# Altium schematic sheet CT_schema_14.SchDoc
size 632 x 434 mm
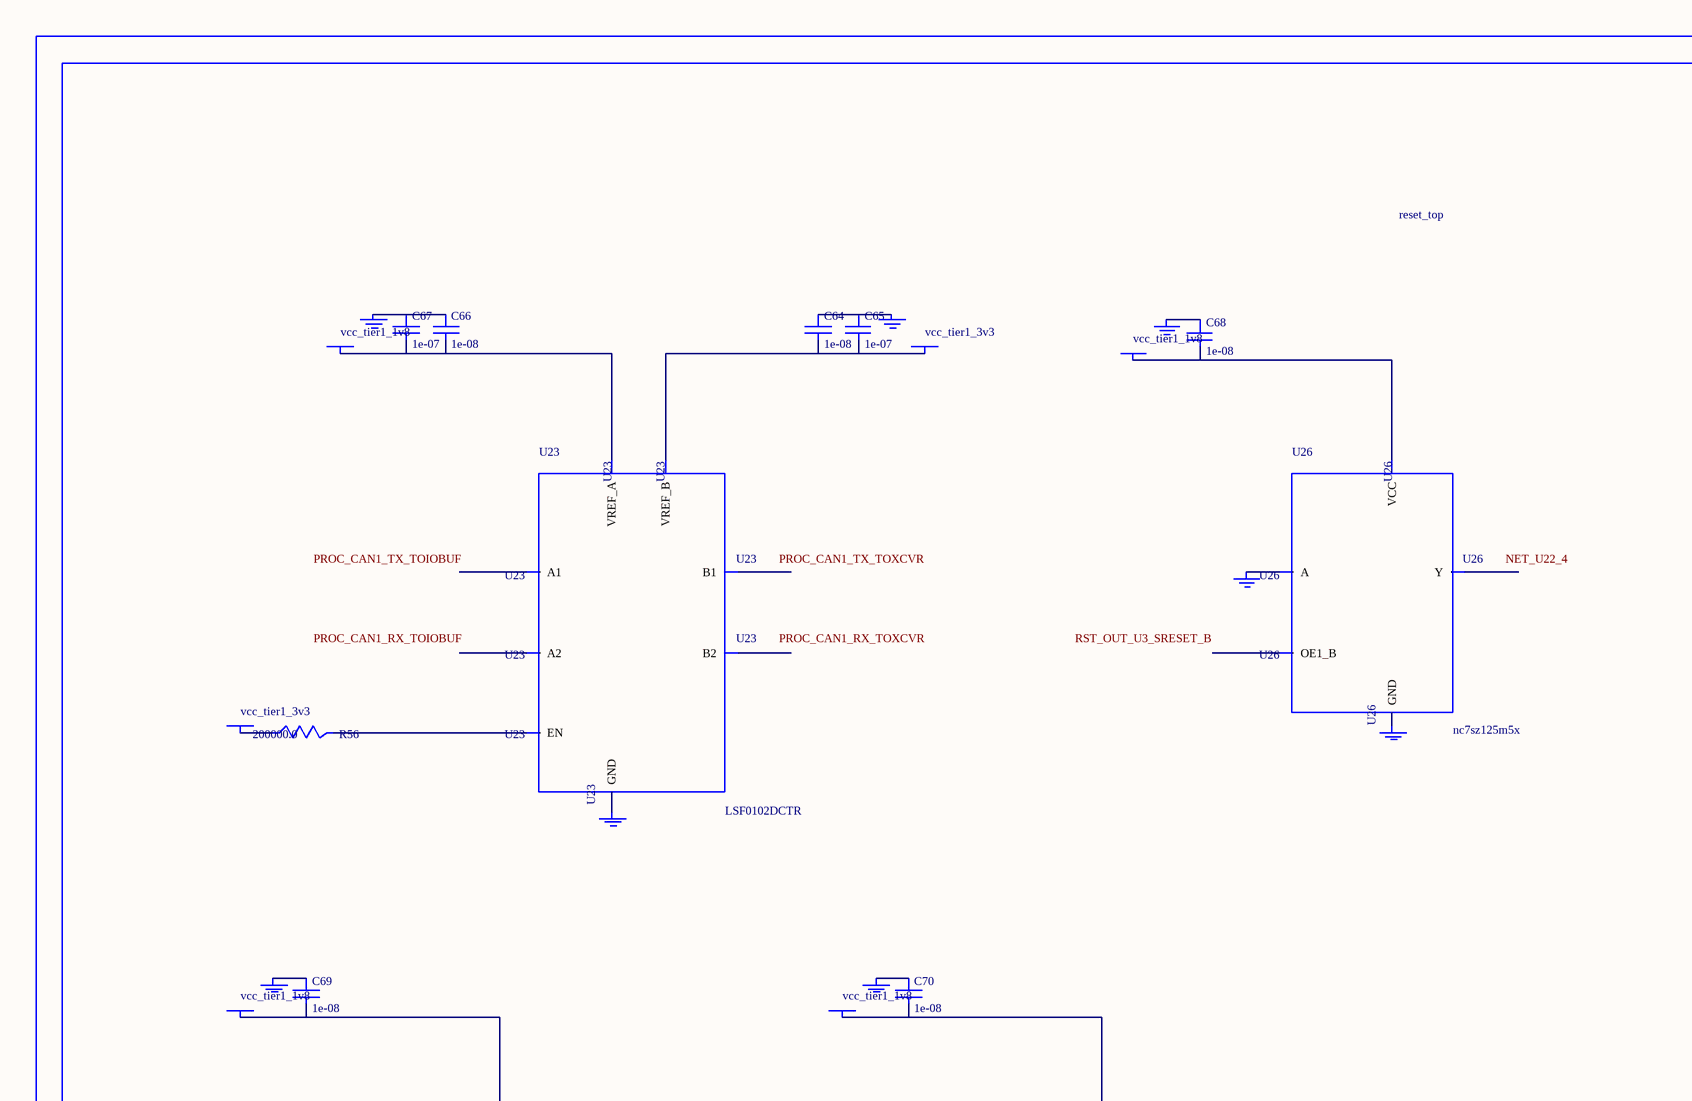
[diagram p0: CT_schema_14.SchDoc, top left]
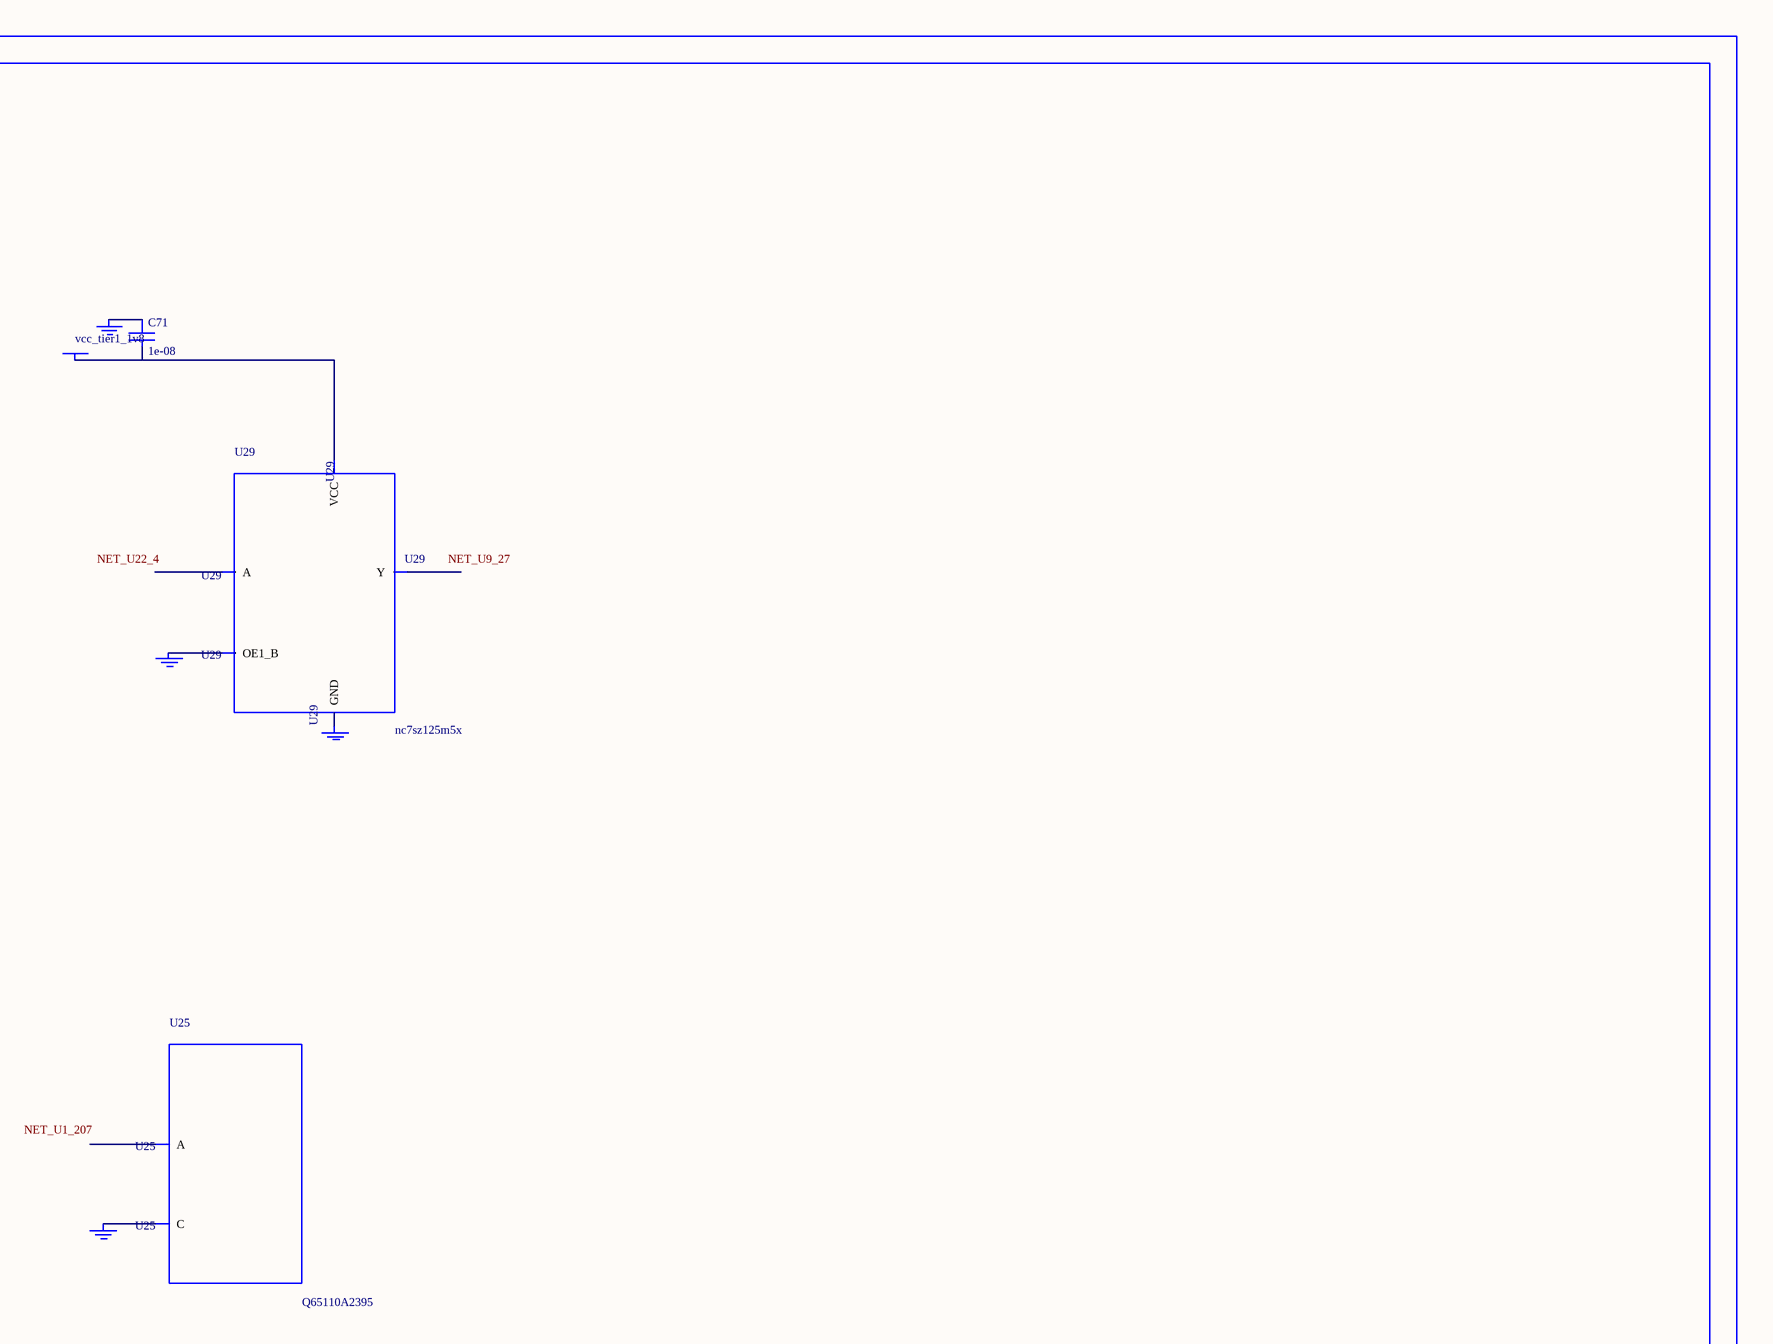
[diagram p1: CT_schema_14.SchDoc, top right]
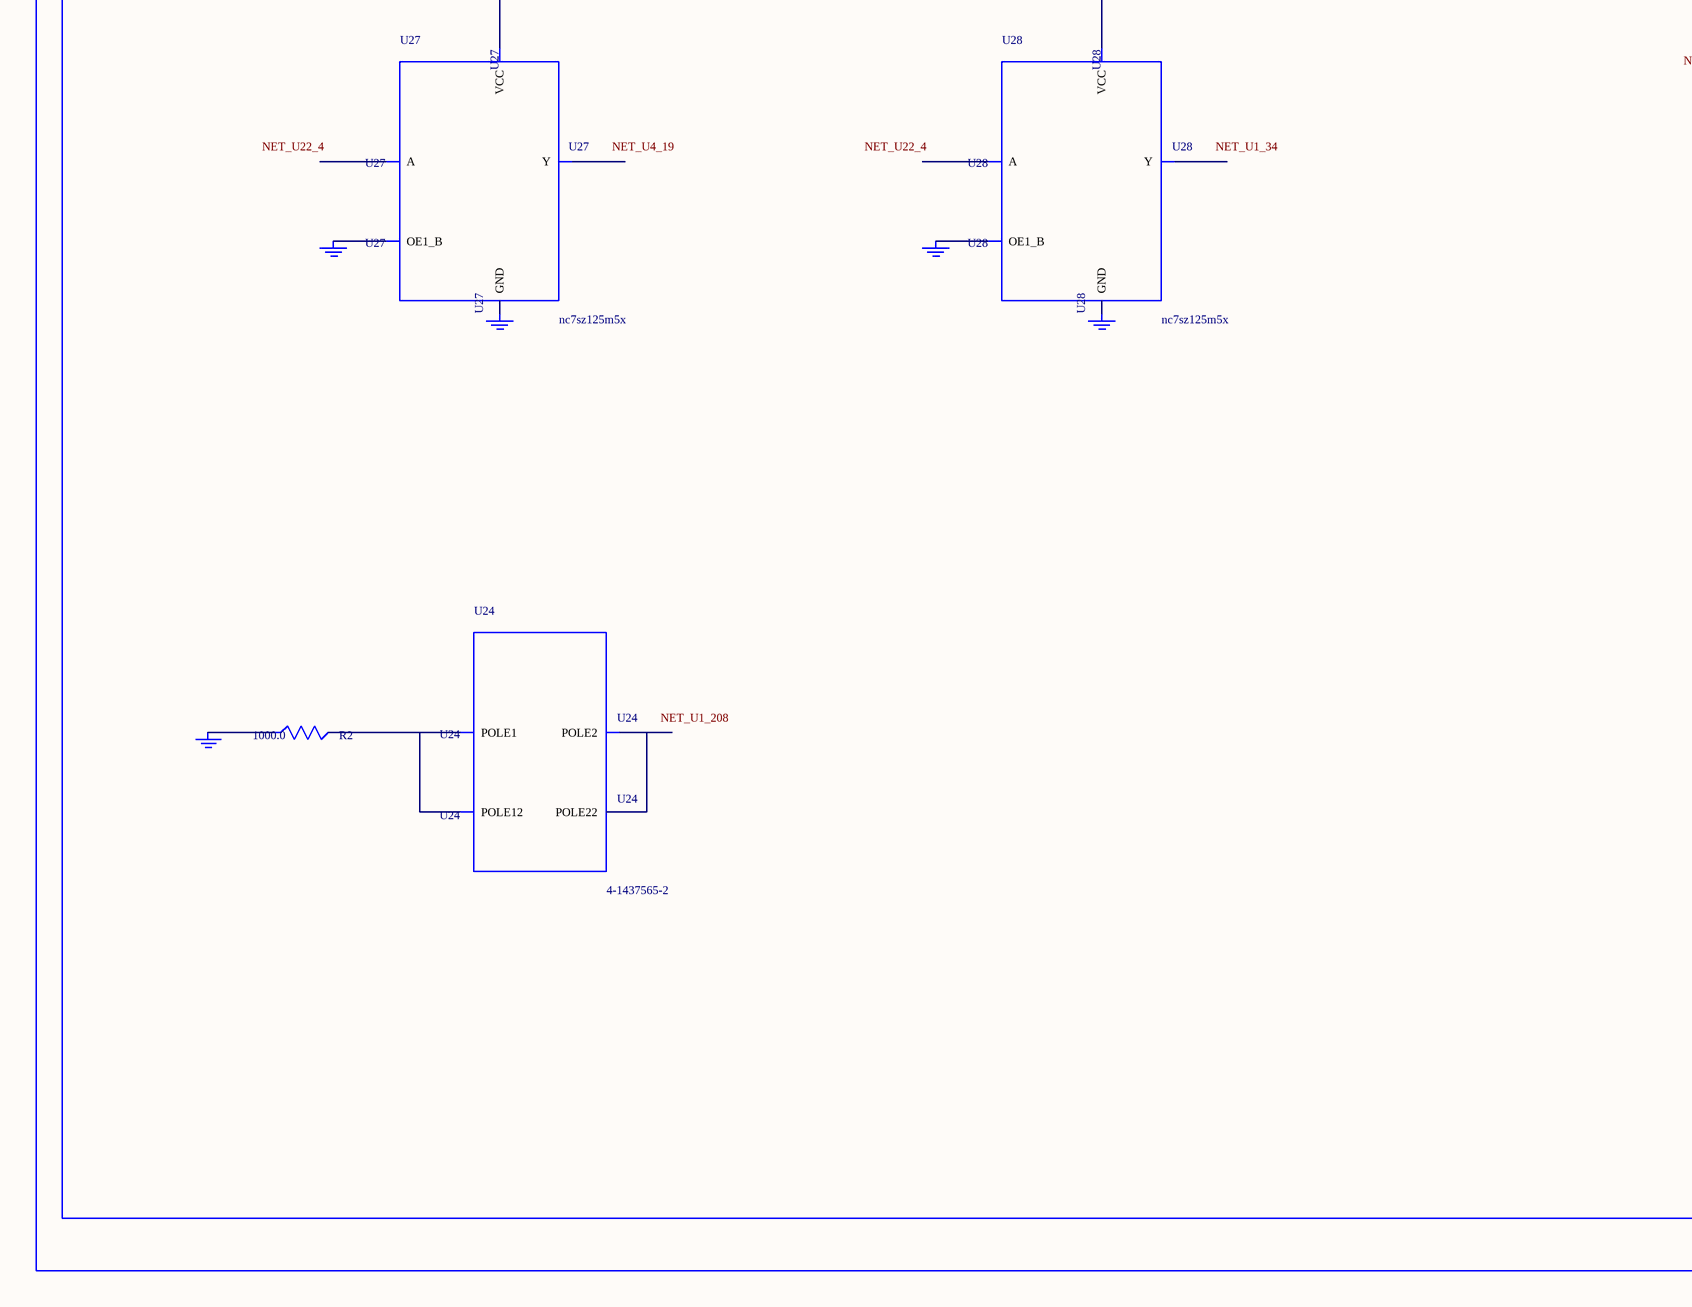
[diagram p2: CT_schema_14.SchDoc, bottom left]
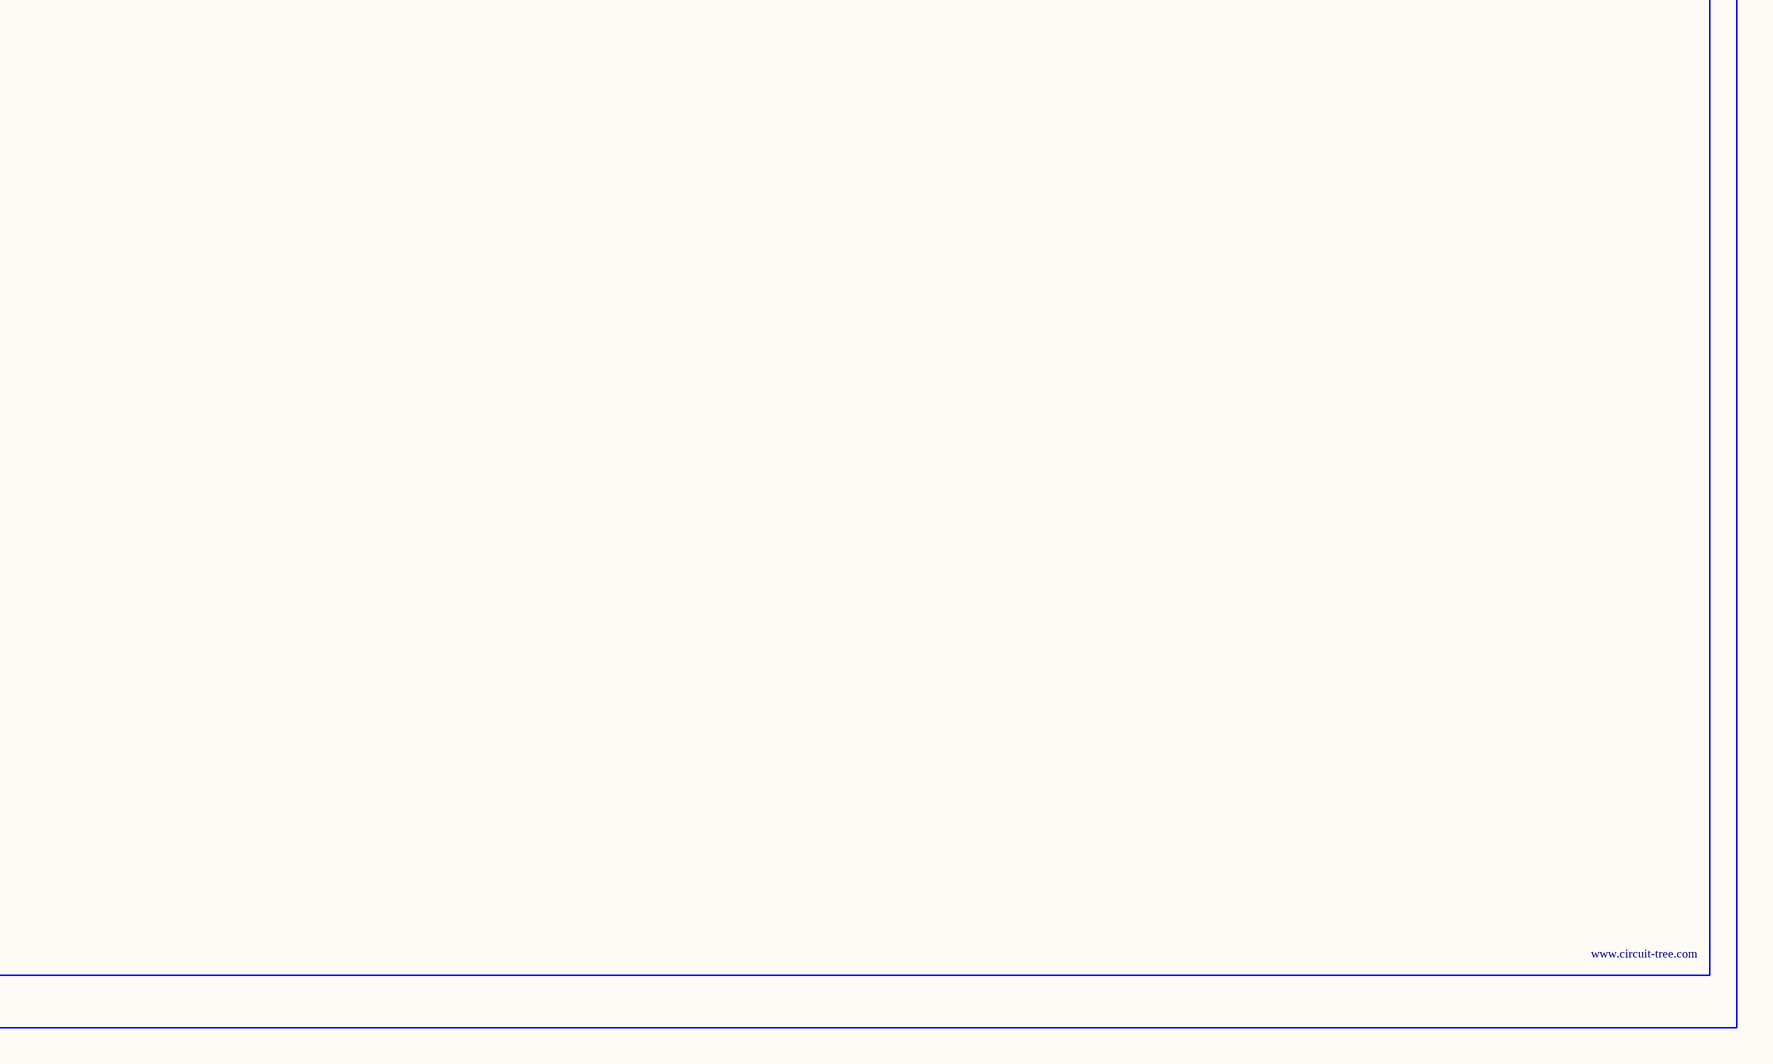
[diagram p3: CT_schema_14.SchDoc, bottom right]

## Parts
BORDER13  (no value)
C64  1e-08  [C0402]
C65  1e-07  [C0402]
C66  1e-08  [C0402]
C67  1e-07  [C0402]
C68  1e-08  [C0402]
C69  1e-08  [C0402]
C70  1e-08  [C0402]
C71  1e-08  [C0402]
GND_INSTANCE_13_0  (no value)
GND_INSTANCE_13_1  (no value)
GND_INSTANCE_13_2  (no value)
GND_INSTANCE_13_3  (no value)
GND_INSTANCE_13_4  (no value)
GND_INSTANCE_13_5  (no value)
GND_INSTANCE_13_6  (no value)
GND_INSTANCE_13_7  (no value)
GND_INSTANCE_13_8  (no value)
GND_INSTANCE_13_9  (no value)
GND_INSTANCE_13_10  (no value)
GND_INSTANCE_13_11  (no value)
GND_INSTANCE_13_12  (no value)
GND_INSTANCE_13_13  (no value)
GND_INSTANCE_13_14  (no value)
GND_INSTANCE_13_15  (no value)
GND_INSTANCE_13_16  (no value)
POWER_INSTANCE_13_0  vcc_tier1_1v8
POWER_INSTANCE_13_1  vcc_tier1_3v3
POWER_INSTANCE_13_2  vcc_tier1_3v3
POWER_INSTANCE_13_3  vcc_tier1_1v8
POWER_INSTANCE_13_4  vcc_tier1_1v8
POWER_INSTANCE_13_5  vcc_tier1_1v8
POWER_INSTANCE_13_6  vcc_tier1_1v8
R2  1000.0  [R0603]
R56  200000.0  [R0603]
U23  LSF0102DCTR  [DCU0008A_N]
U24  4-1437565-2  [SW_4-1437565-2]
U25  Q65110A2395  [LGM67K-G1J2-24-Z]
U26  nc7sz125m5x  [NC7SZ125M5X]
U27  nc7sz125m5x  [NC7SZ125M5X]
U28  nc7sz125m5x  [NC7SZ125M5X]
U29  nc7sz125m5x  [NC7SZ125M5X]

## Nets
NetC64_1: C64.1 C65.1 GND_INSTANCE_13_1.0(GND)
NetC64_2: C64.2 C65.2 POWER_INSTANCE_13_1.0(PWR) U23.7(VREF_B)
NetC66_1: C66.1 C67.1 GND_INSTANCE_13_0.0(GND)
NetC66_2: C66.2 C67.2 POWER_INSTANCE_13_0.0(PWR) U23.2(VREF_A)
NetC68_1: C68.1 GND_INSTANCE_13_5.0(GND)
NetC68_2: C68.2 POWER_INSTANCE_13_3.0(PWR) U26.5(VCC)
NetC69_1: C69.1 GND_INSTANCE_13_8.0(GND)
NetC69_2: C69.2 POWER_INSTANCE_13_4.0(PWR) U27.5(VCC)
NetC70_1: C70.1 GND_INSTANCE_13_11.0(GND)
NetC70_2: C70.2 POWER_INSTANCE_13_5.0(PWR) U28.5(VCC)
NetC71_1: C71.1 GND_INSTANCE_13_14.0(GND)
NetC71_2: C71.2 POWER_INSTANCE_13_6.0(PWR) U29.5(VCC)
NetGND_INSTANCE_13_2_0: GND_INSTANCE_13_2.0(GND) U23.1(GND)
NetGND_INSTANCE_13_3_0: GND_INSTANCE_13_3.0(GND) R2.1
NetGND_INSTANCE_13_4_0: GND_INSTANCE_13_4.0(GND) U25.C
NetGND_INSTANCE_13_6_0: GND_INSTANCE_13_6.0(GND) U26.2(A)
NetGND_INSTANCE_13_7_0: GND_INSTANCE_13_7.0(GND) U26.3(GND)
NetGND_INSTANCE_13_9_0: GND_INSTANCE_13_9.0(GND) U27.1(OE1_B)
NetGND_INSTANCE_13_10_0: GND_INSTANCE_13_10.0(GND) U27.3(GND)
NetGND_INSTANCE_13_12_0: GND_INSTANCE_13_12.0(GND) U28.1(OE1_B)
NetGND_INSTANCE_13_13_0: GND_INSTANCE_13_13.0(GND) U28.3(GND)
NetGND_INSTANCE_13_15_0: GND_INSTANCE_13_15.0(GND) U29.1(OE1_B)
NetGND_INSTANCE_13_16_0: GND_INSTANCE_13_16.0(GND) U29.3(GND)
NetPOWER_INSTANCE_13_2_0: POWER_INSTANCE_13_2.0(PWR) R56.1
NetR2_2: R2.2 U24.1(POLE1) U24.2(POLE12)
NetR56_2: R56.2 U23.8(EN)
NetU24_3: U24.3(POLE2) U24.4(POLE22)

Not connected (* = marked no-connect by the designer): U23 3(A1) 4(A2) 5(B2) 6(B1); U25 A; U26 1(OE1_B) 4(Y); U27 2(A) 4(Y); U28 2(A) 4(Y); U29 2(A) 4(Y)

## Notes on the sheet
- Labels drawn without touching a wire or pin: NET_U1_34, NET_U1_207, NET_U1_208, NET_U4_19, NET_U9_27, NET_U22_4, PROC_CAN1_RX_TOIOBUF, PROC_CAN1_RX_TOXCVR, PROC_CAN1_TX_TOIOBUF, PROC_CAN1_TX_TOXCVR, RST_OUT_U3_SRESET_B

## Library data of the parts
BORDER13 = BORDER_PAGE13
C64 C66 C68-C71 = C0402C103K3RAC
C65 C67 = C0402C104K3RACTU
GND_INSTANCE_13_0-GND_INSTANCE_13_16 = GND
POWER_INSTANCE_13_0-POWER_INSTANCE_13_6 = PWR
R2 = RC0603JR-071KL
R56 = RC0603JR-07200KL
